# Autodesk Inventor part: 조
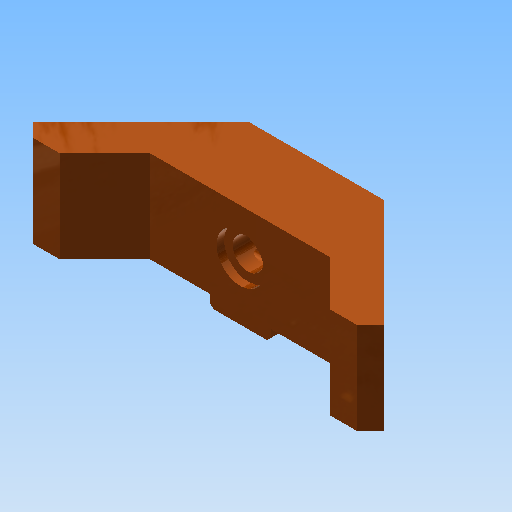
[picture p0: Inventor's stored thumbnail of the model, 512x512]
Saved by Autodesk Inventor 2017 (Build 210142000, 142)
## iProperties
Created: 2019-04
Part Number: 조
Material: 알루미늄 6061
Document SubType Name: Modeling
Designer: mduedu
Density: 1 g/cm^3
Appearance: 매끄러움 - 연한 주황색
Author: mduedu
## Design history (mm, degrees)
sketch "스케치1"
  geometry: L1 (45.962, 0)-(0, -45.962); L2 (0, -45.962)-(-45.962, 0); L3 (-45.962, 0)-(0, 45.962); L4 (0, 45.962)-(45.962, 0); L5 (45.962, 0)-(-45.962, 0); L6 (0, -45.962)-(0, 45.962); 1 further point
  constraints: 12 end point, 2 midpoint, 2 parallel, 2 perpendicular, 1 horizontal
  dimensions: "d0" = 65 distance of L1.end L2.end
extrude "돌출1" new body sketch "스케치1" distance "d2" = 27; taper "d3" = 0 deg
chamfer "모따기1" distance "d4" = 25; stored, may be unused: second distance "d5" = 2, angle "d6" = 45 deg
sketch "스케치2"
  geometry: L1 (-17.678, 28.284)-(-45.962, 0) reference; L2 (-17.678, 28.284)-(17.678, 28.284) reference; L3 (45.962, 0)-(17.678, 28.284) reference; L4 (-45.962, 0)-(0, -45.962) reference; L5 (0, -45.962)-(45.962, 0) reference; L6 (-23.536, 8.284)-(23.536, 8.284); L7 (-23.536, 8.284)-(-38.891, -7.071); L8 (38.891, -7.071)-(23.536, 8.284); 1 further point
  constraints: 6 end point, 3 parallel, 2 point on line
  dimensions: "d7" = 20 distance between parallel lines of L6 L2; "d8" = 10 distance between parallel lines of L1 L7; "d9" = 10 distance between parallel lines of L3 L8
extrude "돌출2" cut sketch "스케치2" stored distance "d10" = 27; taper "d11" = 0 deg
sketch "스케치3"
  geometry: L1 (63.64, -27)-(63.64, 0) reference; L2 (56.569, -27)-(63.64, -27) reference; L3 (-28.284, -27)-(-28.284, 0) reference; L4 (-28.284, -27)-(-21.213, -27) reference; L5 (63.64, -27)-(25.678, -27); L6 (25.678, -27)-(25.678, -24); L7 (25.678, -24)-(63.64, -24); L8 (63.64, -24)-(63.64, -27); L9 (-28.284, -27)-(9.678, -27); L10 (9.678, -27)-(9.678, -24); L11 (9.678, -24)-(-28.284, -24); L12 (-28.284, -24)-(-28.284, -27); L13 (41.213, 0)-(-5.858, 0) reference; L14 (17.678, -27)-(17.678, 0)
  constraints: 18 end point, 4 parallel, 2 horizontal, 2 perpendicular, 1 midpoint, 1 symmetric about line
  dimensions: "d12" = 3 distance between parallel lines of L5 L7; "d14" = 16 distance between parallel lines of L10 L6
extrude "돌출3" cut sketch "스케치3" stored distance "d15" = 27; taper "d16" = 0 deg
sketch "스케치4"
  geometry: L1 (31.536, -27)-(15.536, -27) reference; L2 (31.536, -24)-(47.071, -24) reference; 3 further points
  constraints: 1 midpoint, 1 vertical alignment
  dimensions: "d17" = 12 distance from line of L2 point (23.536, -12)
hole "구멍1" sketch "스케치4" at (23.536, -12) diameter "d18" = 8; stored, may be unused: countersink angle "d22" = 90 deg, drill point angle "d24" = 118 deg; dims "d19" = 6, "d20" = 12.5, "d21" = 2, "d23" = 14
node "작업 평면1"
sketch "스케치5"
  geometry: L1 (0, -15)-(0, 0); L2 (-50, -4)-(50, -4); L3 (50, -4)-(50, -1.75); L4 (-50, -1.75)-(-50, -4); L5 (12, -1.75)-(12, -2.75); L6 (12, -2.75)-(-12, -2.75); L7 (-12, -2.75)-(-12, -1.75); L8 (50, -1.75)-(12, -1.75); L9 (-12, -1.75)-(-50, -1.75); C1 r 4 at (0, 0) reference; 2 further points
  constraints: 18 end point, 4 parallel, 2 midpoint, 2 vertical, 2 vertical alignment, 1 collinear, 1 horizontal, 1 perpendicular, 1 tangent
  dimensions: "d26" = 2.5 diameter of L6 L2; "d28" = 4.5 diameter of L8 L2; "d29" = 24 distance of L5.end L6.end; "d30" = 100 distance between parallel lines of L3 L4
revolve "회전1" sketch "스케치5" stored, may be unused: angle "d31" = 90 deg
chamfer "모따기2" distance "d32" = 5; stored, may be unused: second distance "d33" = 2, angle "d34" = 45 deg
chamfer "모따기3" distance "d35" = 1; stored, may be unused: second distance "d36" = 2, angle "d37" = 45 deg
node "솔리드1"
other parameters: "d25" = -5
